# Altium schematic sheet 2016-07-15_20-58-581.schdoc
size 297 x 111 mm; SheetNumber: 1; SheetTotal: 1
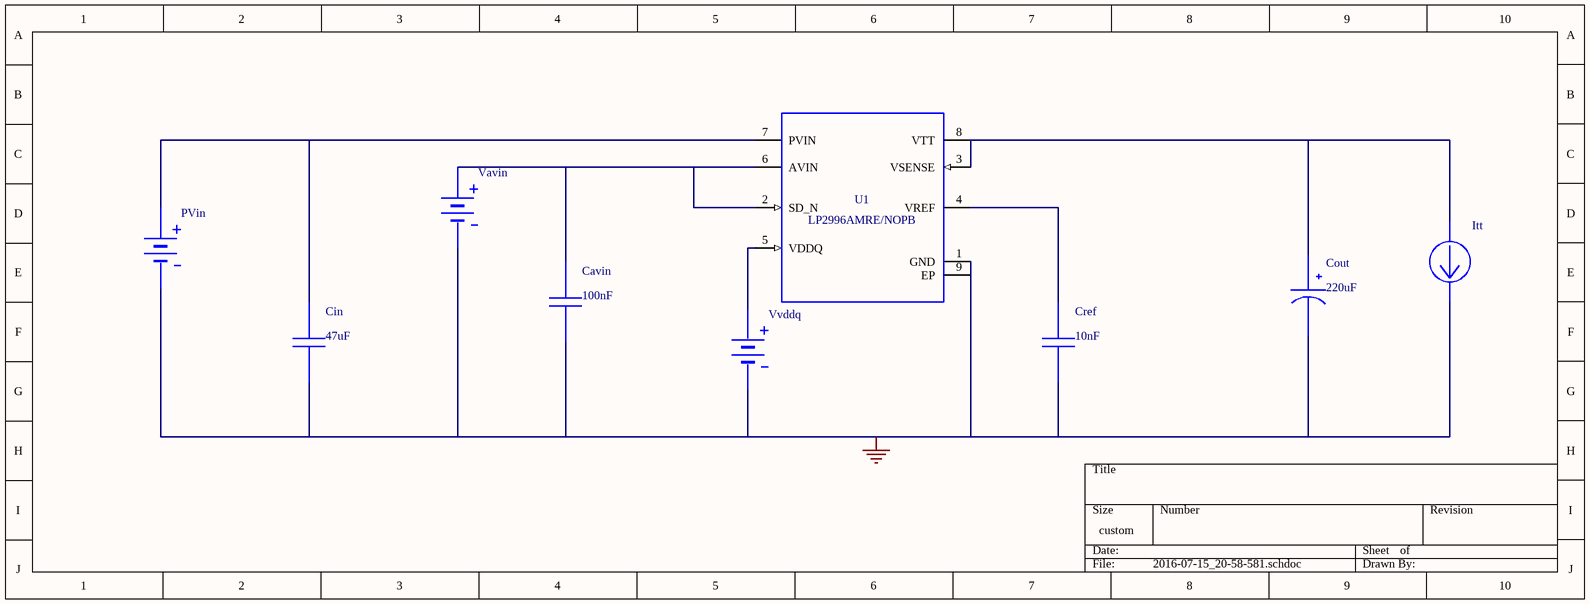
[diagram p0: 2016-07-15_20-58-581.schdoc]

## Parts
Cavin  value 100nF  (hidden comment: GRM155R60J104KA01D)
Cin  value 47uF  (hidden comment: JMK212BJ476MG-T)
Cout  value 220uF  (hidden comment: 2R5TPE220MAFB)
Cref  value 10nF  (hidden comment: GRM155R60J103KA01D)
Itt  WB_CURRENT_LOAD  (value not drawn)
PVin  WB_BATTERY  (value not drawn)
U1  LP2996AMRE/NOPB
Vavin  WB_PRIM_DC_VOLTAGE_SOURCE  (value not drawn)
Vvddq  WB_PRIM_DC_VOLTAGE_SOURCE  (value not drawn)

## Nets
0: Cavin.2 Cin.2 Cout.2(-) Cref.2 Itt.2(-) PVin.2(-) U1.1(GND) U1.9(EP) Vavin.2(-) Vvddq.2(-)
NetCavin_1: Cavin.1 U1.2(SD_N) U1.6(AVIN) Vavin.1(+)
NetCin_1: Cin.1 PVin.1(+) U1.7(PVIN)
NetCout_1: Cout.1(+) Itt.1(+) U1.3(VSENSE) U1.8(VTT)
NetCref_1: Cref.1 U1.4(VREF)
NetU1_5: U1.5(VDDQ) Vvddq.1(+)

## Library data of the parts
Cavin = GRM155R60J104KA01D: GRM155R60J104KA0; Manufacturer Name: MuRata
Cin = JMK212BJ476MG-T: Manufacturer Name: Taiyo Yuden
Cout = 2R5TPE220MAFB: Manufacturer Name: Panasonic
Cref = GRM155R60J103KA01D: GRM155R60J103KA0; Manufacturer Name: MuRata
U1 = LP2996AMRE/NOPB: Manufacturer Name: Texas Instruments
Vavin Vvddq = WB_PRIM_DC_VOLTAGE_SOURCE: WB_PRIM_DC_VOLTA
